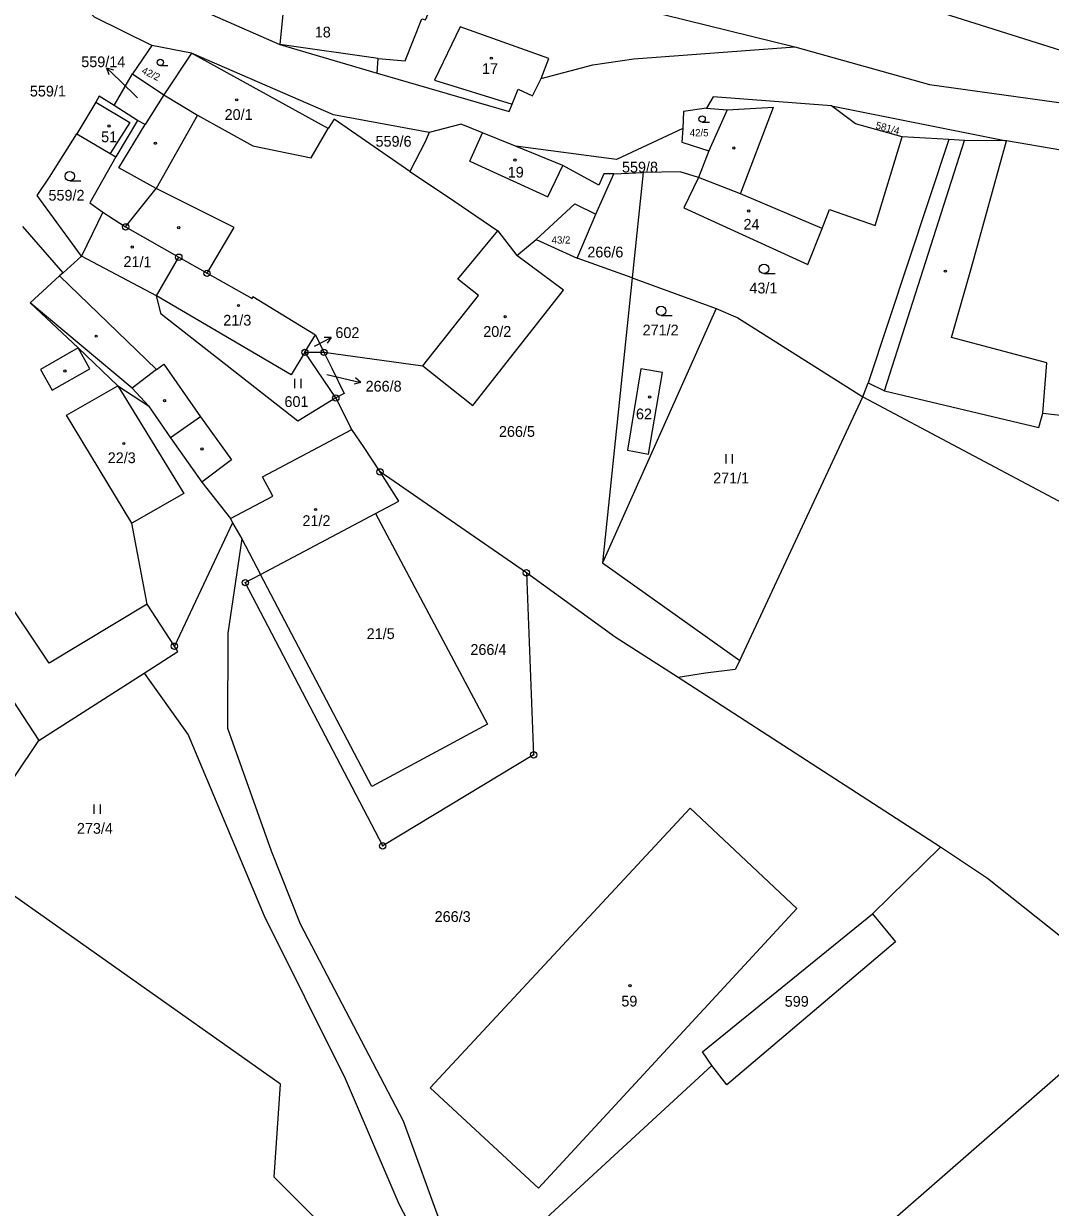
# Model space of a CAD drawing. Extents: x -680203 to -673936, y -1102717 to -1093650.
# Drawn here: x -675523.1 to -675360.8, y -1100092.5 to -1099905.6 of the extents above; entities that cross this region are included whole.
import ezdxf

# ---------------------------------------------------------------- set-up
doc = ezdxf.new("R2010")
doc.units = 0
for name, color, linetype in [('_Ideová část', 7, 'Continuous'), ('SOxx02xx_Koleje_param další_Popis10', 7, 'Continuous'), ('SOxx02xx_Staničení_Popis10', 7, 'Continuous'), ('SOxxxxxx_Koleje_hlavní_body_Popis10', 7, 'Continuous'), ('SOxxxxxx_Koleje_param další_Popis10', 7, 'Continuous'), ('SOxxxxxx_Osa_bod_P', 7, 'Continuous'), ('SOxxxxxx_Staničení_Popis10', 7, 'Continuous'), ('x_prac', 7, 'Continuous')]:
    doc.layers.add(name, color=color, linetype=linetype)

msp = doc.modelspace()

# ---------------------------------------------------------------- linework, layer by layer
at = {"layer": '_Ideová část'}
msp.add_circle((-676417.7, -1099401.52), 1287.12, dxfattribs=at)
at = {"layer": 'SOxx02xx_Koleje_param další_Popis10'}
for centre, radius in [((-675506.94, -1099937.68), 0.5), ((-675506.94, -1099937.68), 0.0303), ((-675498.54, -1099942.47), 0.5), ((-675498.54, -1099942.47), 0.0303), ((-675494.08, -1099945.01), 0.5), ((-675494.08, -1099945.01), 0.0303), ((-675478.61, -1099957.49), 0.5), ((-675478.61, -1099957.49), 0.0303), ((-675475.6, -1099957.48), 0.5), ((-675475.6, -1099957.48), 0.0303), ((-675473.73, -1099964.69), 0.5), ((-675473.73, -1099964.69), 0.0303), ((-675466.74, -1099976.37), 0.5), ((-675466.74, -1099976.37), 0.0303), ((-675443.62, -1099992.3), 0.5), ((-675443.62, -1099992.3), 0.0303), ((-675488.03, -1099993.86), 0.5), ((-675488.03, -1099993.86), 0.0303), ((-675499.24, -1100003.9), 0.5), ((-675499.24, -1100003.9), 0.0303), ((-675442.47, -1100021.06), 0.5), ((-675442.47, -1100021.06), 0.0303), ((-675466.32, -1100035.43), 0.5), ((-675466.32, -1100035.43), 0.0303)]:
    msp.add_circle(centre, radius, dxfattribs=at)
at = {"layer": 'SOxx02xx_Staničení_Popis10'}
for p, q in [((-675507.79, -1099914.64), (-675509.95, -1099912.55)), ((-675509.95, -1099912.55), (-675508.88, -1099912.89)), ((-675509.95, -1099912.55), (-675509.58, -1099913.61)), ((-675505.05, -1099917.29), (-675507.79, -1099914.64)), ((-675477.12, -1099956.52), (-675474.45, -1099955.16)), ((-675474.45, -1099955.16), (-675475.57, -1099955.17)), ((-675474.45, -1099955.16), (-675475.11, -1099956.06)), ((-675475.13, -1099961.01), (-675472.67, -1099961.58)), ((-675472.67, -1099961.58), (-675469.75, -1099962.26)), ((-675469.75, -1099962.26), (-675470.83, -1099962.52)), ((-675469.75, -1099962.26), (-675470.61, -1099961.54))]:
    msp.add_line(p, q, dxfattribs=at)
at = {"layer": 'SOxxxxxx_Koleje_hlavní_body_Popis10'}
for p, q in [((-675501.45, -1099912.21), (-675500.28, -1099912.21)), ((-675415.84, -1099921.14), (-675414.67, -1099921.14)), ((-675515.77, -1099930.42), (-675514.02, -1099930.42)), ((-675406.07, -1099945.06), (-675404.32, -1099945.06)), ((-675422.32, -1099951.7), (-675420.57, -1099951.7)), ((-675480.19, -1099963.17), (-675480.19, -1099961.67)), ((-675479.19, -1099963.17), (-675479.19, -1099961.67)), ((-675412.07, -1099975.05), (-675412.07, -1099973.55)), ((-675411.07, -1099975.05), (-675411.07, -1099973.55)), ((-675511.92, -1100030.38), (-675511.92, -1100028.88)), ((-675510.92, -1100030.38), (-675510.92, -1100028.88))]:
    msp.add_line(p, q, dxfattribs=at)
for centre, radius in [((-675501.46, -1099911.71), 0.502), ((-675415.85, -1099920.64), 0.502), ((-675515.77, -1099929.67), 0.75), ((-675406.07, -1099944.31), 0.75), ((-675422.32, -1099950.95), 0.75)]:
    msp.add_circle(centre, radius, dxfattribs=at)
at = {"layer": 'SOxxxxxx_Koleje_param další_Popis10'}
for centre in [(-675449.16, -1099911.04), (-675489.39, -1099917.62), (-675509.57, -1099921.75), (-675502.24, -1099924.47), (-675410.84, -1099925.21), (-675445.43, -1099927.13), (-675408.48, -1099935.18), (-675498.56, -1099937.82), (-675505.9, -1099940.87), (-675377.41, -1099944.68), (-675489.1, -1099950.09), (-675446.97, -1099951.87), (-675511.6, -1099954.94), (-675516.54, -1099960.44), (-675500.79, -1099965.13), (-675424.15, -1099964.53), (-675507.22, -1099971.89), (-675494.88, -1099972.75), (-675476.93, -1099982.31), (-675427.25, -1100057.5)]:
    msp.add_circle(centre, 0.175, dxfattribs=at)
at = {"layer": 'SOxxxxxx_Staničení_Popis10'}
for p, q in [((-675467.06, -1099911.08), (-675482.56, -1099908.87)), ((-675511.64, -1099917.99), (-675506.29, -1099921.21)), ((-675500.89, -1099916.83), (-675495.61, -1099920.06)), ((-675495.61, -1099920.06), (-675502.13, -1099931.61)), ((-675495.61, -1099920.06), (-675486.84, -1099924.86)), ((-675411.91, -1099919.19), (-675404.58, -1099918.79)), ((-675409.79, -1099932.45), (-675404.58, -1099918.79)), ((-675506.29, -1099921.21), (-675509.38, -1099926.1)), ((-675507.99, -1099928.37), (-675503.85, -1099921.53)), ((-675477.61, -1099926.76), (-675474.92, -1099922.16)), ((-675452.56, -1099927.32), (-675450.54, -1099922.82)), ((-675486.84, -1099924.86), (-675477.61, -1099926.76)), ((-675387.05, -1099963.55), (-675374.4, -1099924.04)), ((-675373.3, -1099944.08), (-675367.74, -1099924.1)), ((-675452.56, -1099927.32), (-675440.25, -1099932.92)), ((-675502.13, -1099931.61), (-675507.99, -1099928.37)), ((-675440.25, -1099932.92), (-675437.83, -1099927.99)), ((-675409.79, -1099932.45), (-675416.4, -1099929.88)), ((-675506.94, -1099937.68), (-675502.13, -1099931.61)), ((-675489.8, -1099937.76), (-675502.13, -1099931.61)), ((-675396.89, -1099937.96), (-675409.79, -1099932.45)), ((-675494.08, -1099945.01), (-675489.8, -1099937.76)), ((-675502.07, -1099948.57), (-675513.92, -1099942.29)), ((-675376.46, -1099955.13), (-675373.3, -1099944.08)), ((-675517.38, -1099945.43), (-675502.05, -1099960.22)), ((-675505.9, -1099963.16), (-675522.02, -1099949.68)), ((-675361.35, -1099959.13), (-675376.46, -1099955.13)), ((-675514.42, -1099956.8), (-675520.38, -1099960.21)), ((-675512.6, -1099960.07), (-675514.42, -1099956.8)), ((-675502.05, -1099960.22), (-675500.89, -1099959.34)), ((-675500.89, -1099959.34), (-675495.12, -1099967.65)), ((-675362.03, -1099967.08), (-675361.35, -1099959.13)), ((-675520.38, -1099960.21), (-675518.54, -1099963.47)), ((-675518.54, -1099963.47), (-675512.6, -1099960.07)), ((-675502.05, -1099960.22), (-675505.9, -1099963.16)), ((-675508.17, -1099962.77), (-675497.74, -1099979.77)), ((-675505.9, -1099963.16), (-675503.31, -1099965.95)), ((-675495.12, -1099967.65), (-675499.85, -1099970.97)), ((-675495.12, -1099967.65), (-675490.21, -1099974.46)), ((-675490.21, -1099974.46), (-675494.91, -1099977.97)), ((-675497.74, -1099979.77), (-675505.94, -1099984.47)), ((-675519.02, -1100006.55), (-675530.05, -1099990.14)), ((-675503.53, -1099997.24), (-675519.02, -1100006.55))]:
    msp.add_line(p, q, dxfattribs=at)
at = {"layer": 'x_prac'}
for p, q in [((-675481.7, -1099899.82), (-675482.56, -1099908.87)), ((-675428.81, -1099902.44), (-675401.21, -1099909.23)), ((-675482.56, -1099908.87), (-675467.22, -1099913.4)), ((-675502.8, -1099909.05), (-675505.86, -1099913.5)), ((-675496.53, -1099910.27), (-675502.8, -1099909.05)), ((-675496.53, -1099910.27), (-675500.89, -1099916.83)), ((-675508.74, -1099918.52), (-675505.86, -1099913.5)), ((-675505.86, -1099913.5), (-675500.89, -1099916.83)), ((-675505.04, -1099920.87), (-675508.74, -1099918.52)), ((-675395.42, -1099918.58), (-675367.74, -1099924.1)), ((-675505.04, -1099920.87), (-675508.49, -1099926.62)), ((-675376.86, -1099923.88), (-675384.22, -1099923.45)), ((-675414.76, -1099925.69), (-675416.4, -1099929.88)), ((-675376.86, -1099923.88), (-675389.6, -1099962.3)), ((-675432.62, -1099935.68), (-675429.77, -1099929.3)), ((-675429.77, -1099929.3), (-675425.16, -1099929.07)), ((-675425.16, -1099929.07), (-675426.91, -1099945.75)), ((-675510.55, -1099935.37), (-675513.92, -1099942.29)), ((-675510.55, -1099935.37), (-675506.94, -1099937.68)), ((-675435.58, -1099942.62), (-675432.62, -1099935.68)), ((-675516.8, -1099944.96), (-675523.17, -1099937.64)), ((-675506.94, -1099937.68), (-675498.54, -1099942.47)), ((-675448.13, -1099938.32), (-675445.1, -1099942.18)), ((-675445.1, -1099942.18), (-675442.09, -1099939.68)), ((-675442.09, -1099939.68), (-675435.58, -1099942.62)), ((-675513.92, -1099942.29), (-675516.8, -1099944.96)), ((-675502.07, -1099948.57), (-675498.54, -1099942.47)), ((-675426.91, -1099945.75), (-675435.58, -1099942.62)), ((-675426.91, -1099945.75), (-675431.57, -1099990.73)), ((-675426.91, -1099945.75), (-675413.6, -1099950.55)), ((-675413.6, -1099950.55), (-675431.57, -1099990.73)), ((-675478.61, -1099957.49), (-675476.94, -1099954.72)), ((-675476.94, -1099954.72), (-675475.6, -1099957.48)), ((-675514.42, -1099956.8), (-675508.17, -1099962.77)), ((-675478.61, -1099957.49), (-675475.6, -1099957.48)), ((-675473.73, -1099964.69), (-675478.61, -1099957.49)), ((-675475.6, -1099957.48), (-675459.96, -1099959.64)), ((-675390.43, -1099964.52), (-675389.6, -1099962.3)), ((-675471.22, -1099969.67), (-675473.73, -1099964.69)), ((-675409.91, -1100006.14), (-675390.43, -1099964.52)), ((-675485.32, -1099977.15), (-675471.22, -1099969.67)), ((-675483.69, -1099980.2), (-675485.32, -1099977.15)), ((-675443.62, -1099992.3), (-675466.74, -1099976.37)), ((-675490.39, -1099983.75), (-675483.69, -1099980.2)), ((-675485.62, -1099992.58), (-675467.44, -1099982.95)), ((-675490.03, -1099984.39), (-675499.24, -1100003.9)), ((-675490.39, -1099983.75), (-675490.03, -1099984.39)), ((-675490.03, -1099984.39), (-675488.6, -1099986.94)), ((-675488.6, -1099986.94), (-675485.62, -1099992.58)), ((-675431.57, -1099990.73), (-675409.91, -1100006.14)), ((-675443.62, -1099992.3), (-675442.47, -1100021.06)), ((-675535.78, -1099995.73), (-675520.68, -1100018.76)), ((-675520.68, -1100018.76), (-675504.01, -1100008.13)), ((-675378.15, -1100035.65), (-675419.61, -1100008.83)), ((-675378.15, -1100035.65), (-675388.9, -1100046.15)), ((-675400.9, -1100045.3), (-675441.72, -1100089.46)), ((-675414.33, -1100070.11), (-675451.95, -1100104.77))]:
    msp.add_line(p, q, dxfattribs=at)
for points in [[(-675502.8, -1099909.05), (-675511.85, -1099904.57), (-675515.39, -1099901.22), (-675517.72, -1099896.74), (-675517.87, -1099890.68), (-675512.06, -1099877.6), (-675503.62, -1099862.76)], [(-675311.02, -1099930.79), (-675322.46, -1099922.4), (-675340.64, -1099915.67), (-675425.14, -1099889.01)], [(-675497.49, -1099897.54), (-675494.57, -1099903.62), (-675482.56, -1099908.87)], [(-675467.22, -1099913.4), (-675467.06, -1099911.08), (-675462.78, -1099911.46), (-675460.14, -1099904.84), (-675459.54, -1099904.98), (-675457.81, -1099900.97), (-675468.38, -1099897.08)], [(-675441.29, -1099914.24), (-675440.05, -1099911.1), (-675454.07, -1099906.07), (-675458.12, -1099914.5), (-675445.88, -1099918.29)], [(-675458.96, -1099922.77), (-675474.07, -1099919.97), (-675496.53, -1099910.27)], [(-675462.02, -1099928.91), (-675473.99, -1099920.67), (-675474.92, -1099922.16), (-675496.53, -1099910.27)], [(-675441.29, -1099914.24), (-675433.12, -1099912.1), (-675426.66, -1099911.13), (-675401.21, -1099909.23)], [(-675401.21, -1099909.23), (-675379.93, -1099915.21), (-675356.41, -1099918.44), (-675336.69, -1099924.06), (-675311.02, -1099930.79)], [(-675467.22, -1099913.4), (-675446.35, -1099919.45), (-675445.88, -1099918.29)], [(-675445.88, -1099918.29), (-675444.89, -1099915.93), (-675442.64, -1099916.98), (-675441.29, -1099914.24)], [(-675508.74, -1099918.52), (-675511.1, -1099917.03), (-675511.64, -1099917.99), (-675514.66, -1099923.01)], [(-675500.89, -1099916.83), (-675503.85, -1099921.53), (-675505.04, -1099920.87)], [(-675395.42, -1099918.58), (-675414.11, -1099917.13), (-675415.14, -1099918.93)], [(-675415.14, -1099918.93), (-675418.77, -1099919.48), (-675418.88, -1099922.13)], [(-675415.14, -1099918.93), (-675411.91, -1099919.19), (-675414.76, -1099925.69)], [(-675384.22, -1099923.45), (-675391.61, -1099921.41), (-675395.42, -1099918.58)], [(-675445.33, -1099924.94), (-675450.54, -1099922.82), (-675453.91, -1099921.45), (-675458.96, -1099922.77)], [(-675513.92, -1099942.29), (-675520.91, -1099932.71), (-675518.95, -1099929.84), (-675514.66, -1099923.01)], [(-675514.66, -1099923.01), (-675509.38, -1099926.1), (-675508.49, -1099926.62)], [(-675458.96, -1099922.77), (-675459.62, -1099924.25), (-675462.02, -1099928.91)], [(-675418.88, -1099922.13), (-675429.35, -1099927.06), (-675445.33, -1099924.94)], [(-675418.88, -1099922.13), (-675419.06, -1099924.3), (-675414.76, -1099925.69)], [(-675416.4, -1099929.88), (-675418.72, -1099934.68), (-675399.14, -1099943.62), (-675396.89, -1099937.96), (-675395.73, -1099934.93), (-675388.49, -1099937.44), (-675384.22, -1099923.45)], [(-675429.77, -1099929.3), (-675431.4, -1099929.3), (-675432.14, -1099931.1), (-675437.83, -1099927.99), (-675445.33, -1099924.94)], [(-675367.74, -1099924.1), (-675374.4, -1099924.04), (-675376.86, -1099923.88)], [(-675319.75, -1099935.36), (-675348.73, -1099928.19), (-675359.16, -1099925.59), (-675367.74, -1099924.1)], [(-675508.49, -1099926.62), (-675512.62, -1099933.88), (-675510.55, -1099935.37)], [(-675462.02, -1099928.91), (-675456.26, -1099932.8), (-675448.13, -1099938.32)], [(-675416.4, -1099929.88), (-675419.34, -1099928.97), (-675425.16, -1099929.07)], [(-675442.09, -1099939.68), (-675435.94, -1099934.05), (-675432.62, -1099935.68)], [(-675459.96, -1099959.64), (-675451.19, -1099948.52), (-675454.45, -1099945.95), (-675448.13, -1099938.32)], [(-675498.54, -1099942.47), (-675494.08, -1099945.01), (-675486.97, -1099948.97), (-675486.83, -1099948.69), (-675476.94, -1099954.72)], [(-675459.96, -1099959.64), (-675452.06, -1099965.9), (-675437.76, -1099947.69), (-675445.1, -1099942.18)], [(-675516.8, -1099944.96), (-675517.38, -1099945.43), (-675522.02, -1099949.68), (-675514.42, -1099956.8)], [(-675473.73, -1099964.69), (-675479.74, -1099968.34), (-675501.3, -1099951.47), (-675502.07, -1099948.57)], [(-675478.61, -1099957.49), (-675480.76, -1099961.04), (-675502.07, -1099948.57)], [(-675413.6, -1099950.55), (-675410.2, -1099952.05), (-675390.43, -1099964.52)], [(-675389.6, -1099962.3), (-675387.05, -1099963.55), (-675362.63, -1099969.38), (-675362.03, -1099967.08), (-675351.79, -1099968.27), (-675347.27, -1099952.53), (-675341.64, -1099955.18)], [(-675475.6, -1099957.48), (-675474.36, -1099959.99), (-675472.43, -1099964), (-675473.73, -1099964.69)], [(-675422.12, -1099960.68), (-675425.52, -1099960.11), (-675427.66, -1099972.94), (-675424.31, -1099973.55), (-675422.12, -1099960.68)], [(-675499.24, -1100003.9), (-675503.53, -1099997.24), (-675505.94, -1099984.47), (-675516.3, -1099967.43), (-675508.17, -1099962.77)], [(-675508.17, -1099962.77), (-675503.31, -1099965.95), (-675499.85, -1099970.97), (-675494.91, -1099977.97), (-675490.39, -1099983.75)], [(-675390.43, -1099964.52), (-675358.76, -1099981.37), (-675350.92, -1099982.83)], [(-675466.74, -1099976.37), (-675469.23, -1099972.53), (-675471.22, -1099969.67)], [(-675467.44, -1099982.95), (-675463.76, -1099980.99), (-675466.74, -1099976.37)], [(-675467.44, -1099982.95), (-675449.77, -1100016.19), (-675468.06, -1100026.07), (-675485.62, -1099992.58)], [(-675488.6, -1099986.94), (-675490.8, -1100001.83), (-675490.85, -1100016.83), (-675483.97, -1100036.22), (-675479.36, -1100047.75), (-675463.07, -1100078.83), (-675456.93, -1100095.79), (-675451.95, -1100104.77)], [(-675442.47, -1100021.06), (-675466.32, -1100035.43), (-675488.03, -1099993.86), (-675485.62, -1099992.58)], [(-675419.61, -1100008.83), (-675429.58, -1100002.45), (-675443.62, -1099992.3)], [(-675504.01, -1100008.13), (-675498.7, -1100004.74), (-675499.24, -1100003.9)], [(-675409.91, -1100006.14), (-675410.62, -1100007.59), (-675415.3, -1100008.17), (-675419.61, -1100008.83)], [(-675504.01, -1100008.13), (-675497.05, -1100017.87), (-675485.06, -1100046.49), (-675472.26, -1100072.14), (-675463.76, -1100091.96), (-675446.93, -1100124.36)], [(-675545.92, -1100053.79), (-675532.43, -1100036.29), (-675520.68, -1100018.76)], [(-675441.72, -1100089.46), (-675458.8, -1100073.63), (-675417.72, -1100029.49), (-675400.9, -1100045.3)], [(-675227.61, -1100140.95), (-675258.46, -1100125.54), (-675331.04, -1100072.09), (-675370.73, -1100040.57), (-675378.15, -1100035.65)], [(-675446.93, -1100124.36), (-675483.47, -1100087.73), (-675482.46, -1100073.03), (-675526.45, -1100042.02), (-675541.96, -1100056.8)], [(-675414.33, -1100070.11), (-675415.79, -1100067.93), (-675388.9, -1100046.15)], [(-675388.9, -1100046.15), (-675385.31, -1100050.58), (-675411.94, -1100073.17), (-675414.33, -1100070.11)], [(-675317.7, -1100086.57), (-675391.04, -1100152.33), (-675424.81, -1100128.59), (-675349.68, -1100063.08), (-675317.7, -1100086.57)]]:
    msp.add_lwpolyline(points, dxfattribs=at)

# ---------------------------------------------------------------- texts
at = {"layer": 'SOxxxxxx_Osa_bod_P'}
for s, height, p in [('18', 1.7, (-675477.05, -1099907.77)), ('559/14', 1.7, (-675513.95, -1099912.46)), ('17', 1.7, (-675450.62, -1099913.53)), ('559/1', 1.7, (-675522.07, -1099917.09)), ('20/1', 1.7, (-675491.3, -1099920.79)), ('51', 1.7, (-675510.81, -1099924.31)), ('559/6', 1.7, (-675467.45, -1099925.02)), ('42/5', 1.14, (-675417.8, -1099923.39)), ('559/8', 1.7, (-675428.51, -1099929.1)), ('19', 1.7, (-675446.56, -1099929.9)), ('559/2', 1.7, (-675519.13, -1099933.54)), ('24', 1.7, (-675409.31, -1099938.12)), ('43/2', 1.14, (-675439.63, -1099940.32)), ('266/6', 1.7, (-675433.98, -1099942.51)), ('43/1', 1.7, (-675408.37, -1099948.19)), ('21/3', 1.7, (-675491.51, -1099953.27)), ('602', 1.7, (-675473.79, -1099955.23)), ('20/2', 1.7, (-675450.43, -1099955.05)), ('271/2', 1.7, (-675425.25, -1099954.82)), ('266/8', 1.7, (-675469.02, -1099963.69)), ('601', 1.7, (-675481.84, -1099966.12)), ('62', 1.7, (-675426.3, -1099968.07)), ('266/5', 1.7, (-675447.95, -1099970.84)), ('22/3', 1.7, (-675509.77, -1099974.99)), ('271/1', 1.7, (-675414.1, -1099978.18)), ('21/2', 1.7, (-675479, -1099984.92)), ('21/5', 1.7, (-675468.85, -1100002.77)), ('266/4', 1.7, (-675452.46, -1100005.27)), ('273/4', 1.7, (-675514.64, -1100033.51)), ('266/3', 1.7, (-675458.11, -1100047.44)), ('59', 1.7, (-675428.61, -1100060.79)), ('599', 1.7, (-675402.79, -1100060.83))]:
    msp.add_text(s, height=height, dxfattribs=at).set_placement(p)
for s, height, rotation, p in [('42/2', 1.14, 334, (-675504.52, -1099913.37)), ('581/4', 1.14, 345, (-675388.51, -1099922.14)), ('21/1', 1.7, 359, (-675507.29, -1099944))]:
    msp.add_text(s, height=height, rotation=rotation, dxfattribs=at).set_placement(p)

doc.saveas('drawing.dxf')
